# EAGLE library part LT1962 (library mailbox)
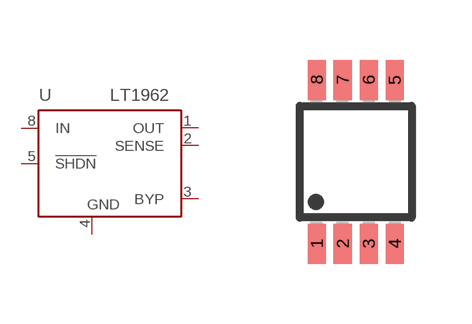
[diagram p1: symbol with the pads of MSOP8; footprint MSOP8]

Designator prefix -

## LT1962  [MSOP8]
1  OUT  pas
2  SENSE  in
3  BYP  in
4  GND  pwr
5  !SHDN  in
8  IN  in

## Footprint MSOP8 (pad centres in mm)
Micro Small Outline Package Grid .65mm
smd 0.45 x 1: 1 -0.975,-2.05; 2 -0.325,-2.05; 3 0.325,-2.05; 4 0.975,-2.05; 5 0.975,2.05; 6 0.325,2.05; 7 -0.325,2.05; 8 -0.975,2.05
